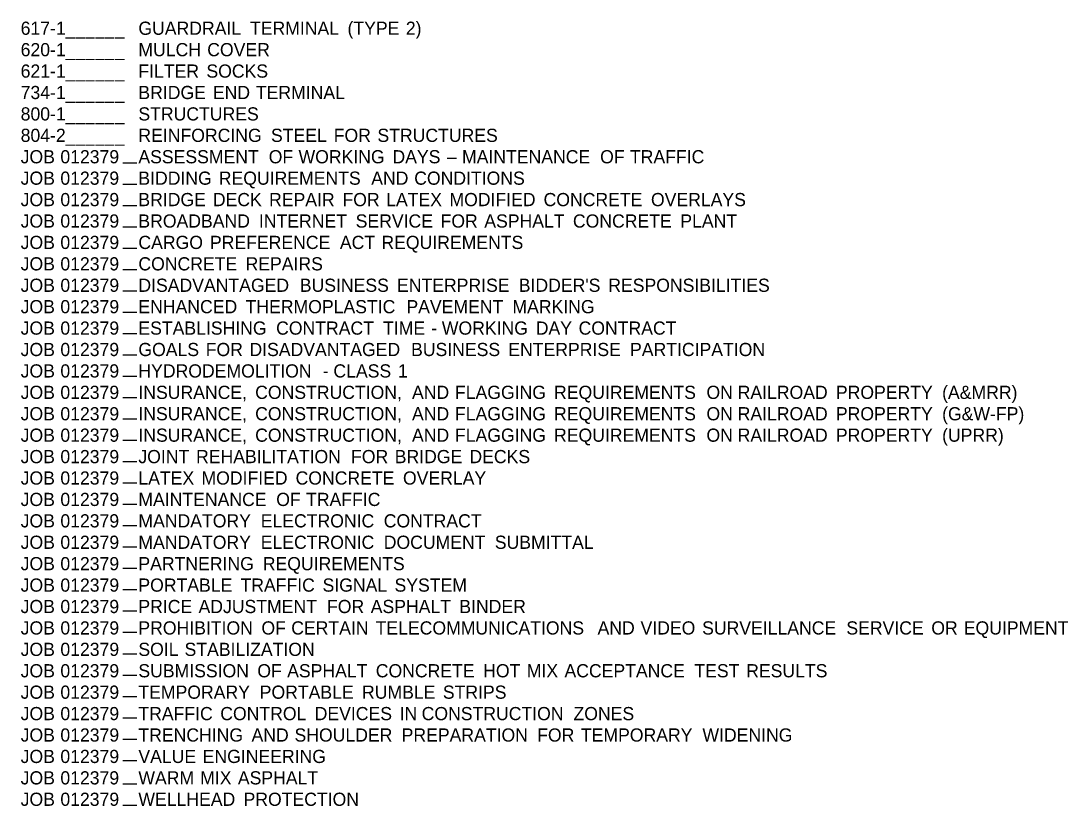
# Model space of a CAD drawing. Extents: x 1930579 to 1935504, y 596431 to 597414.
# Drawn here: x 1934073 to 1934645, y 596524 to 596953 of the extents above; entities that cross this region are included whole.
import ezdxf

# ---------------------------------------------------------------- set-up
doc = ezdxf.new("R2010")
doc.units = 0
doc.layers.add('Default', color=7, linetype='Continuous')
doc.layers.add('R_Border', color=7, linetype='Continuous')

msp = doc.modelspace()

# ---------------------------------------------------------------- linework, layer by layer
at = {"layer": 'R_Border'}
for p, q in [((1934128.37, 596875.49), (1934136.05, 596875.49)), ((1934128.37, 596863.83), (1934136.05, 596863.83)), ((1934128.37, 596852.17), (1934136.05, 596852.17)), ((1934128.37, 596840.51), (1934136.05, 596840.51)), ((1934128.37, 596828.85), (1934136.05, 596828.85)), ((1934128.37, 596817.18), (1934136.05, 596817.18)), ((1934128.37, 596805.52), (1934136.05, 596805.52)), ((1934128.37, 596793.86), (1934136.05, 596793.86)), ((1934128.37, 596782.2), (1934136.05, 596782.2)), ((1934128.37, 596770.54), (1934136.05, 596770.54)), ((1934128.37, 596758.87), (1934136.05, 596758.87)), ((1934128.37, 596747.21), (1934136.05, 596747.21)), ((1934128.37, 596735.55), (1934136.05, 596735.55)), ((1934128.37, 596723.89), (1934136.05, 596723.89)), ((1934128.37, 596712.23), (1934136.05, 596712.23)), ((1934128.37, 596700.56), (1934136.05, 596700.56)), ((1934128.37, 596688.9), (1934136.05, 596688.9)), ((1934128.37, 596677.24), (1934136.05, 596677.24)), ((1934128.37, 596665.58), (1934136.05, 596665.58)), ((1934128.37, 596653.92), (1934136.05, 596653.92)), ((1934128.37, 596642.25), (1934136.05, 596642.25)), ((1934128.37, 596630.59), (1934136.05, 596630.59)), ((1934128.37, 596618.93), (1934136.05, 596618.93)), ((1934128.37, 596607.27), (1934136.05, 596607.27)), ((1934128.37, 596595.61), (1934136.05, 596595.61)), ((1934128.37, 596583.94), (1934136.05, 596583.94)), ((1934128.37, 596572.28), (1934136.05, 596572.28)), ((1934128.37, 596560.62), (1934136.05, 596560.62)), ((1934128.37, 596548.96), (1934136.05, 596548.96)), ((1934128.37, 596536.11), (1934136.05, 596536.11)), ((1934128.37, 596524.57), (1934136.05, 596524.57))]:
    msp.add_line(p, q, dxfattribs=at)

# ---------------------------------------------------------------- texts
at = {"layer": 'Default'}
for s, p in [('617-1______', (1934072.59, 596945.34)), ('GUARDRAIL', (1934136.94, 596945.34)), (' TERMINAL', (1934195.28, 596945.34)), (' (TYPE', (1934248.59, 596945.34)), (' 2)', (1934280.47, 596945.34)), ('620-1______', (1934072.59, 596933.64)), ('MULCH', (1934136.94, 596933.64)), (' COVER', (1934171.9, 596933.64)), ('621-1______', (1934072.59, 596921.94)), ('FILTER', (1934136.94, 596921.94)), (' SOCKS', (1934171.46, 596921.94)), ('734-1______', (1934072.59, 596910.24)), ('BRIDGE', (1934136.94, 596910.24)), (' END', (1934174.98, 596910.24)), (' TERMINAL', (1934198.48, 596910.24)), ('800-1______', (1934072.59, 596898.54)), ('STRUCTURES', (1934136.94, 596898.54)), ('804-2______', (1934072.59, 596886.84)), ('REINFORCING', (1934136.94, 596886.84)), (' STEEL', (1934206.74, 596886.84)), (' FOR', (1934241.05, 596886.84)), (' STRUCTURES', (1934264.94, 596886.84)), ('JOB', (1934072.59, 596875.14)), (' 012379', (1934091.62, 596875.14)), ('ASSESSMENT', (1934136.94, 596875.14)), (' OF', (1934205.51, 596875.14)), (' WORKING', (1934221.82, 596875.14)), (' DAYS', (1934273.16, 596875.14)), (' MAINTENANCE', (1934311.19, 596875.14)), (' OF', (1934386.68, 596875.14)), (' TRAFFIC', (1934402.98, 596875.14)), ('–', (1934305.62, 596875.14)), ('JOB', (1934072.59, 596863.44)), (' 012379', (1934091.62, 596863.44)), ('BIDDING', (1934136.94, 596863.44)), (' REQUIREMENTS', (1934178.23, 596863.44)), (' AND', (1934261.55, 596863.44)), (' CONDITIONS', (1934285.05, 596863.44)), ('JOB', (1934072.59, 596851.74)), (' 012379', (1934091.62, 596851.74)), ('BRIDGE', (1934136.94, 596851.74)), (' DECK', (1934174.98, 596851.74)), (' REPAIR', (1934205.7, 596851.74)), (' FOR', (1934245.82, 596851.74)), (' LATEX', (1934269.71, 596851.74)), (' MODIFIED', (1934304.31, 596851.74)), (' CONCRETE', (1934355.75, 596851.74)), (' OVERLAYS', (1934414.47, 596851.74)), ('JOB', (1934072.59, 596840.04)), (' 012379', (1934091.62, 596840.04)), ('BROADBAND', (1934136.94, 596840.04)), (' INTERNET', (1934200.14, 596840.04)), (' SERVICE', (1934253.04, 596840.04)), (' FOR', (1934299.46, 596840.04)), (' ASPHALT', (1934323.36, 596840.04)), (' CONCRETE', (1934371.8, 596840.04)), (' PLANT', (1934430.51, 596840.04)), ('JOB', (1934072.59, 596828.34)), (' 012379', (1934091.62, 596828.34)), ('CARGO', (1934136.94, 596828.34)), (' PREFERENCE', (1934173.39, 596828.34)), (' ACT', (1934244.41, 596828.34)), (' REQUIREMENTS', (1934267.12, 596828.34)), ('JOB', (1934072.59, 596816.64)), (' 012379', (1934091.62, 596816.64)), ('CONCRETE', (1934136.94, 596816.64)), (' REPAIRS', (1934192.86, 596816.64)), ('JOB', (1934072.59, 596804.94)), (' 012379', (1934091.62, 596804.94)), ('DISADVANTAGED', (1934136.94, 596804.94)), (' BUSINESS', (1934222.5, 596804.94)), (' ENTERPRISE', (1934275.65, 596804.94)), (" BIDDER'S", (1934342.2, 596804.94)), (' RESPONSIBILITIES', (1934391.12, 596804.94)), ('JOB', (1934072.59, 596793.24)), (' 012379', (1934091.62, 596793.24)), ('ENHANCED', (1934136.94, 596793.24)), (' THERMOPLASTIC', (1934192.87, 596793.24)), (' PAVEMENT', (1934280.79, 596793.24)), (' MARKING', (1934338.73, 596793.24)), ('JOB', (1934072.59, 596781.54)), (' 012379', (1934091.62, 596781.54)), ('ESTABLISHING', (1934136.94, 596781.54)), (' CONTRACT', (1934209.55, 596781.54)), (' TIME', (1934268.03, 596781.54)), (' WORKING', (1934300.15, 596781.54)), (' DAY', (1934351.49, 596781.54)), (' CONTRACT', (1934374.9, 596781.54)), (' -', (1934294.32, 596781.54)), ('JOB', (1934072.59, 596769.84)), (' 012379', (1934091.62, 596769.84)), ('GOALS', (1934136.94, 596769.84)), (' FOR', (1934171.08, 596769.84)), (' DISADVANTAGED', (1934194.98, 596769.84)), (' BUSINESS', (1934283.33, 596769.84)), (' ENTERPRISE', (1934336.48, 596769.84)), (' PARTICIPATION', (1934403.03, 596769.84)), ('JOB', (1934072.59, 596758.14)), (' 012379', (1934091.62, 596758.14)), ('HYDRODEMOLITION', (1934136.94, 596758.14)), (' CLASS', (1934240.88, 596758.14)), (' 1', (1934276.14, 596758.14)), (' -', (1934235.05, 596758.14)), ('JOB', (1934072.59, 596746.44)), (' 012379', (1934091.62, 596746.44)), ('INSURANCE,', (1934136.94, 596746.44)), (' CONSTRUCTION,', (1934198.1, 596746.44)), (' AND', (1934283.83, 596746.44)), (' FLAGGING', (1934307.33, 596746.44)), (' REQUIREMENTS', (1934361.48, 596746.44)), (' ON', (1934444.8, 596746.44)), (' RAILROAD', (1934461.86, 596746.44)), (' PROPERTY', (1934515.55, 596746.44)), (' (A&MRR)', (1934573.62, 596746.44)), (' (G&W-FP)', (1934573.62, 596734.74)), ('JOB', (1934072.59, 596734.74)), (' 012379', (1934091.62, 596734.74)), ('INSURANCE,', (1934136.94, 596734.74)), (' CONSTRUCTION,', (1934198.1, 596734.74)), (' AND', (1934283.83, 596734.74)), (' FLAGGING', (1934307.33, 596734.74)), (' REQUIREMENTS', (1934361.48, 596734.74)), (' ON', (1934444.8, 596734.74)), (' RAILROAD', (1934461.86, 596734.74)), (' PROPERTY', (1934515.55, 596734.74)), ('JOB', (1934072.59, 596723.04)), (' 012379', (1934091.62, 596723.04)), ('INSURANCE,', (1934136.94, 596723.04)), (' CONSTRUCTION,', (1934198.1, 596723.04)), (' AND', (1934283.83, 596723.04)), (' FLAGGING', (1934307.33, 596723.04)), (' REQUIREMENTS', (1934361.48, 596723.04)), (' ON', (1934444.8, 596723.04)), (' RAILROAD', (1934461.86, 596723.04)), (' PROPERTY', (1934515.55, 596723.04)), (' (UPRR)', (1934573.62, 596723.04)), ('JOB', (1934072.59, 596711.34)), (' 012379', (1934091.62, 596711.34)), ('JOINT', (1934136.94, 596711.34)), (' REHABILITATION', (1934165.8, 596711.34)), (' FOR', (1934250.51, 596711.34)), (' BRIDGE', (1934274.4, 596711.34)), (' DECKS', (1934315.23, 596711.34)), ('JOB', (1934072.59, 596699.64)), (' 012379', (1934091.62, 596699.64)), ('LATEX', (1934136.94, 596699.64)), (' MODIFIED', (1934168.75, 596699.64)), (' CONCRETE', (1934220.19, 596699.64)), (' OVERLAY', (1934278.9, 596699.64)), ('JOB', (1934072.59, 596687.94)), (' 012379', (1934091.62, 596687.94)), ('MAINTENANCE', (1934136.94, 596687.94)), (' OF', (1934209.63, 596687.94)), (' TRAFFIC', (1934225.94, 596687.94)), ('JOB', (1934072.59, 596676.24)), (' 012379', (1934091.62, 596676.24)), ('MANDATORY', (1934136.94, 596676.24)), (' ELECTRONIC', (1934201.15, 596676.24)), (' CONTRACT', (1934268.39, 596676.24)), ('JOB', (1934072.59, 596664.54)), (' 012379', (1934091.62, 596664.54)), ('MANDATORY', (1934136.94, 596664.54)), (' ELECTRONIC', (1934201.15, 596664.54)), (' DOCUMENT', (1934268.39, 596664.54)), (' SUBMITTAL', (1934329.1, 596664.54)), ('JOB', (1934072.59, 596652.84)), (' 012379', (1934091.62, 596652.84)), ('PARTNERING', (1934136.94, 596652.84)), (' REQUIREMENTS', (1934202.27, 596652.84)), ('JOB', (1934072.59, 596641.14)), (' 012379', (1934091.62, 596641.14)), ('PORTABLE', (1934136.94, 596641.14)), (' TRAFFIC', (1934190.08, 596641.14)), (' SIGNAL', (1934234.95, 596641.14)), (' SYSTEM', (1934274.29, 596641.14)), ('JOB', (1934072.59, 596629.44)), (' 012379', (1934091.62, 596629.44)), ('PRICE', (1934136.94, 596629.44)), (' ADJUSTMENT', (1934167.15, 596629.44)), (' FOR', (1934237.38, 596629.44)), (' ASPHALT', (1934261.27, 596629.44)), (' BINDER', (1934309.71, 596629.44)), ('JOB', (1934072.59, 596617.74)), (' 012379', (1934091.62, 596617.74)), ('PROHIBITION', (1934136.94, 596617.74)), (' OF', (1934201.52, 596617.74)), (' CERTAIN', (1934217.82, 596617.74)), (' TELECOMMUNICATIONS', (1934263.95, 596617.74)), (' AND', (1934385.28, 596617.74)), (' VIDEO', (1934408.77, 596617.74)), (' SURVEILLANCE', (1934442.43, 596617.74)), (' SERVICE', (1934521.28, 596617.74)), (' OR', (1934567.71, 596617.74)), (' EQUIPMENT', (1934585.45, 596617.74)), ('JOB', (1934072.59, 596606.04)), (' 012379', (1934091.62, 596606.04)), ('SOIL', (1934136.94, 596606.04)), (' STABILIZATION', (1934159.51, 596606.04)), ('JOB', (1934072.59, 596594.34)), (' 012379', (1934091.62, 596594.34)), ('SUBMISSION', (1934136.94, 596594.34)), (' OF', (1934199.29, 596594.34)), (' ASPHALT', (1934215.59, 596594.34)), (' CONCRETE', (1934264.03, 596594.34)), (' HOT', (1934322.75, 596594.34)), (' MIX', (1934346.58, 596594.34)), (' ACCEPTANCE', (1934367.19, 596594.34)), (' TEST', (1934438.21, 596594.34)), (' RESULTS', (1934466.52, 596594.34)), ('JOB', (1934072.59, 596582.64)), (' 012379', (1934091.62, 596582.64)), ('TEMPORARY', (1934136.94, 596582.64)), (' PORTABLE', (1934200.59, 596582.64)), (' RUMBLE', (1934256.53, 596582.64)), (' STRIPS', (1934300.71, 596582.64)), ('JOB', (1934072.59, 596570.94)), (' 012379', (1934091.62, 596570.94)), ('TRAFFIC', (1934136.94, 596570.94)), (' CONTROL', (1934179.02, 596570.94)), (' DEVICES', (1934230.64, 596570.94)), (' IN', (1934277.08, 596570.94)), (' CONSTRUCTION', (1934289.11, 596570.94)), (' ZONES', (1934372.12, 596570.94)), ('JOB', (1934072.59, 596559.24)), (' 012379', (1934091.62, 596559.24)), ('TRENCHING', (1934136.94, 596559.24)), (' AND', (1934196.12, 596559.24)), (' SHOULDER', (1934219.62, 596559.24)), (' PREPARATION', (1934278.18, 596559.24)), (' FOR', (1934352.27, 596559.24)), (' TEMPORARY', (1934376.16, 596559.24)), (' WIDENING', (1934442.61, 596559.24)), ('JOB', (1934072.59, 596547.54)), (' 012379', (1934091.62, 596547.54)), ('VALUE', (1934136.94, 596547.54)), (' ENGINEERING', (1934169.4, 596547.54)), ('JOB', (1934072.59, 596535.84)), (' 012379', (1934091.62, 596535.84)), ('WARM', (1934136.94, 596535.84)), (' MIX', (1934168.04, 596535.84)), (' ASPHALT', (1934188.65, 596535.84)), ('JOB', (1934072.59, 596524.14)), (' 012379', (1934091.62, 596524.14)), ('WELLHEAD', (1934136.94, 596524.14)), (' PROTECTION', (1934191.75, 596524.14))]:
    msp.add_text(s, height=7.2, dxfattribs=at).set_placement(p)

doc.saveas('drawing.dxf')
